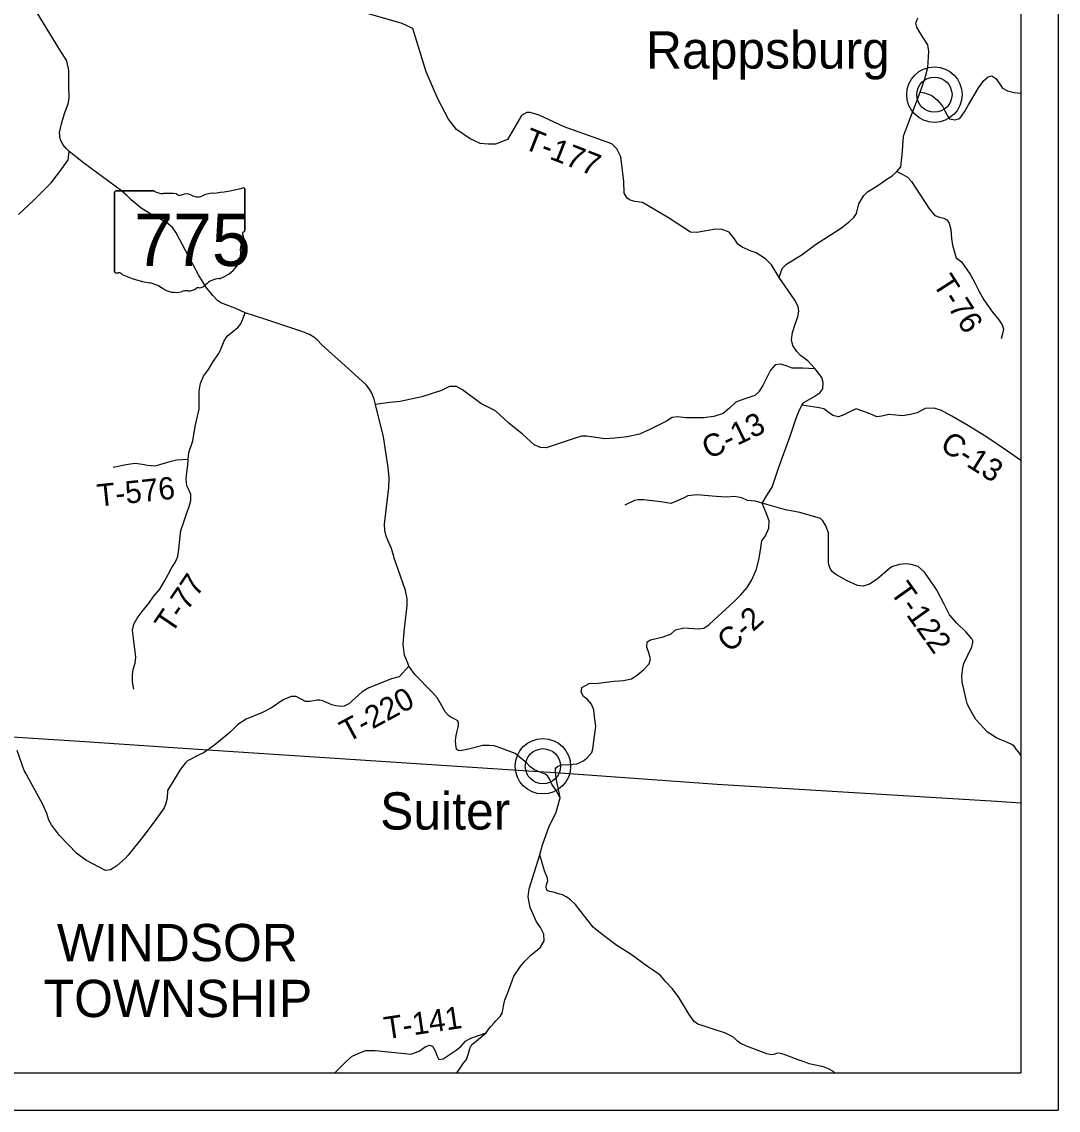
# Model space of a CAD drawing. Extents: x 0 to 34, y 0 to 22.
# Drawn here: x 6.219 to 9, y 14 to 16.922 of the extents above; entities that cross this region are included whole.
import ezdxf

# ---------------------------------------------------------------- set-up
doc = ezdxf.new("R2010")
doc.units = 0
for name, color, linetype in [('GM_X_County_Road', 7, 'Continuous'), ('GM_X_County_Road_Text', 7, 'Continuous'), ('GM_X_State_Route', 7, 'Continuous'), ('GM_X_State_Shield', 7, 'Continuous'), ('GM_X_Township', 7, 'Continuous'), ('GM_X_Township_Road', 7, 'Continuous'), ('GM_X_Township_Road_Text', 7, 'Continuous'), ('GM_X_Township_Text', 7, 'Continuous'), ('GM_X_Unincorporated', 7, 'Continuous'), ('SH_Data', 7, 'Continuous'), ('SH_Masking', 7, 'Continuous')]:
    doc.layers.add(name, color=color, linetype=linetype)

msp = doc.modelspace()

# ---------------------------------------------------------------- linework, layer by layer
at = {"layer": 'GM_X_County_Road'}
for points in [[(7.6514, 14.9162), (7.6514, 14.9181), (7.6562, 14.9229), (7.6669, 14.9268), (7.6883, 14.928), (7.7082, 14.9299), (7.7248, 14.9367), (7.7347, 14.9448), (7.7484, 14.96), (7.751, 14.9704), (7.7543, 14.9907), (7.7591, 15.0309), (7.7554, 15.0556), (7.754, 15.0746), (7.7476, 15.0902), (7.7356, 15.1032), (7.7258, 15.1109), (7.7201, 15.1223), (7.7214, 15.1316), (7.7217, 15.1344), (7.7411, 15.145), (7.7654, 15.1464), (7.8083, 15.1518), (7.8337, 15.1536), (7.8553, 15.1581), (7.8709, 15.1682), (7.8881, 15.1833), (7.9022, 15.1977), (7.9061, 15.2114), (7.9012, 15.2277), (7.8964, 15.2426), (7.8972, 15.257), (7.9063, 15.2626), (7.9398, 15.2708), (7.961, 15.2787), (7.9732, 15.2893), (7.9956, 15.2945), (8.0354, 15.292), (8.0495, 15.2938), (8.0624, 15.3032), (8.0769, 15.3165), (8.1078, 15.3448), (8.1306, 15.3652), (8.1482, 15.3837), (8.165, 15.4026), (8.1776, 15.4234), (8.1903, 15.4519), (8.1976, 15.4822), (8.2016, 15.5095), (8.2047, 15.5281), (8.2143, 15.5417), (8.2231, 15.5626), (8.224, 15.582), (8.2143, 15.6078), (8.2057, 15.6291), (8.2229, 15.6575), (8.2325, 15.6723), (8.2491, 15.7235), (8.281, 15.8091), (8.2972, 15.8573), (8.3041, 15.8755), (8.3123, 15.8927), (8.3172, 15.8993), (8.3465, 15.917), (8.3602, 15.9257), (8.3682, 15.9363), (8.369, 15.9534), (8.3661, 15.9663), (8.3477, 15.9897), (8.3277, 16.0117), (8.3084, 16.0258), (8.2982, 16.0369), (8.2881, 16.0522), (8.2847, 16.0674), (8.2871, 16.0875), (8.2929, 16.1068), (8.3014, 16.1292), (8.3041, 16.1451), (8.3019, 16.1573), (8.2937, 16.1744), (8.2512, 16.235), (8.2593, 16.2589), (8.2707, 16.2706), (8.313, 16.297), (8.3491, 16.3234), (8.391, 16.3501), (8.4184, 16.3686), (8.4409, 16.3859), (8.4519, 16.3958), (8.4588, 16.4071), (8.465, 16.4325), (8.4784, 16.4552), (8.4883, 16.4654), (8.5157, 16.482), (8.5378, 16.4971), (8.5545, 16.508), (8.5656, 16.5175), (8.5671, 16.5193), (8.5774, 16.5322), (8.5822, 16.574), (8.5835, 16.6039), (8.5859, 16.6172), (8.5963, 16.646), (8.6298, 16.7328), (8.6421, 16.7688), (8.6502, 16.7984), (8.6531, 16.8421), (8.6502, 16.8599), (8.637, 16.8805), (8.6265, 16.8961), (8.6209, 16.9068), (8.6179, 16.9174), (8.6233, 16.9322)], [(8.6298, 16.7328), (8.6411, 16.7305), (8.6612, 16.7236), (8.6763, 16.7113), (8.6891, 16.6946), (8.6954, 16.6824), (8.703, 16.6694), (8.7086, 16.6614), (8.7222, 16.6583), (8.7363, 16.6616), (8.7481, 16.6802), (8.7589, 16.6987), (8.7738, 16.7226), (8.7864, 16.7442), (8.8002, 16.7642), (8.8116, 16.7737), (8.8219, 16.7767), (8.8328, 16.7694), (8.8411, 16.7564), (8.8505, 16.7431), (8.8641, 16.7358), (8.8819, 16.7315), (8.9, 16.7302)], [(6.2103, 16.4042), (6.2518, 16.4439), (6.2979, 16.4889), (6.3266, 16.5267), (6.343, 16.5513), (6.3462, 16.5736)], [(8.3477, 15.9897), (8.3135, 15.992), (8.2862, 15.9918), (8.2726, 15.9968), (8.2559, 16.0026), (8.2404, 16.0007), (8.2278, 15.986), (8.2071, 15.9455), (8.1971, 15.9284), (8.1857, 15.9186), (8.1561, 15.9089), (8.1352, 15.9003), (8.118, 15.884), (8.1009, 15.8704), (8.0762, 15.8618), (8.0485, 15.8582), (8.0181, 15.8583), (8.0007, 15.858), (7.9791, 15.8612), (7.9639, 15.8594), (7.9491, 15.8496), (7.9046, 15.827), (7.8765, 15.815), (7.8431, 15.8076), (7.8104, 15.8035), (7.7835, 15.8022), (7.7528, 15.8069), (7.7342, 15.8092), (7.7206, 15.8093), (7.7035, 15.8041), (7.6264, 15.7779), (7.6108, 15.7791), (7.5934, 15.786), (7.5629, 15.815), (7.5255, 15.8445), (7.4897, 15.8769), (7.4503, 15.8965), (7.4013, 15.9332), (7.3858, 15.9427), (7.3664, 15.9428), (7.3451, 15.9319), (7.292, 15.9151), (7.2346, 15.9025), (7.2066, 15.8996), (7.1682, 15.8942)], [(8.9, 15.7435), (8.864, 15.7686), (8.8054, 15.8084), (8.7551, 15.8398), (8.7143, 15.8628), (8.6871, 15.8781), (8.6674, 15.8843), (8.6432, 15.8836), (8.6219, 15.8716), (8.604, 15.8671), (8.582, 15.8642), (8.5642, 15.8658), (8.5456, 15.8674), (8.527, 15.8626), (8.5137, 15.8615), (8.4956, 15.8692), (8.4577, 15.8823), (8.441, 15.8748), (8.425, 15.8661), (8.4102, 15.8613), (8.3955, 15.8648), (8.3819, 15.8743), (8.3713, 15.8827), (8.3584, 15.8855), (8.3123, 15.8927)], [(7.6635, 14.8385), (7.6593, 14.861), (7.6534, 14.8861), (7.6512, 14.9069), (7.6514, 14.9162)], [(7.3864, 14.1), (7.3864, 14.1006), (7.3949, 14.1131), (7.4029, 14.1252), (7.412, 14.1358), (7.4178, 14.1521), (7.4209, 14.1654), (7.4267, 14.1764), (7.4335, 14.1817), (7.4646, 14.2081), (7.4705, 14.2157), (7.4778, 14.2247), (7.4862, 14.2349), (7.4909, 14.2398), (7.497, 14.2463), (7.503, 14.2516), (7.5077, 14.2602), (7.5093, 14.2682), (7.5111, 14.2796), (7.5152, 14.296), (7.5226, 14.3137), (7.5396, 14.3597), (7.556, 14.3851), (7.5694, 14.4013), (7.5854, 14.4168), (7.5983, 14.4266), (7.6038, 14.4314), (7.6109, 14.4376), (7.6208, 14.4543), (7.6194, 14.4729), (7.6112, 14.49), (7.6003, 14.5056), (7.5831, 14.5441), (7.5779, 14.5726), (7.5803, 14.5942), (7.6086, 14.6853)]]:
    msp.add_lwpolyline(points, dxfattribs=at)
at = {"layer": 'GM_X_State_Route'}
msp.add_lwpolyline([(8.4009, 14.1), (8.3976, 14.1026), (8.3838, 14.1109), (8.3699, 14.1162), (8.3488, 14.1206), (8.3314, 14.1241), (8.3183, 14.1298), (8.3022, 14.1351), (8.265, 14.1498), (8.2545, 14.1523), (8.2458, 14.1529), (8.237, 14.1494), (8.2297, 14.1488), (8.2181, 14.1514), (8.1633, 14.1722), (8.1468, 14.1798), (8.1394, 14.1857), (8.1294, 14.1951), (8.1197, 14.2003), (8.1055, 14.2079), (8.0826, 14.2149), (8.0634, 14.2212), (8.0442, 14.2274), (8.0334, 14.2314), (8.0233, 14.2378), (8.0098, 14.2567), (7.9815, 14.3046), (7.9639, 14.3271), (7.9466, 14.3453), (7.9315, 14.3628), (7.917, 14.3731), (7.898, 14.3857), (7.8538, 14.4177), (7.8154, 14.4422), (7.7835, 14.4666), (7.7586, 14.4858), (7.7519, 14.4917), (7.7292, 14.5212), (7.7043, 14.5518), (7.6914, 14.5651), (7.6817, 14.5722), (7.6701, 14.5778), (7.6592, 14.5807), (7.6453, 14.5849), (7.6347, 14.5867), (7.6291, 14.5899), (7.6266, 14.5945), (7.6256, 14.5987), (7.6269, 14.6059), (7.6302, 14.6157), (7.63, 14.6229), (7.6214, 14.6421), (7.6086, 14.6853), (7.6165, 14.7124), (7.6334, 14.7598), (7.6525, 14.8003), (7.6635, 14.8385), (7.6525, 14.8585), (7.6413, 14.8754), (7.6351, 14.8892), (7.6295, 14.8976), (7.623, 14.9024), (7.6051, 14.9095), (7.5949, 14.9136), (7.5825, 14.9226), (7.5738, 14.9311), (7.5426, 14.9578), (7.5, 14.9733), (7.4861, 14.9778), (7.4732, 14.9793), (7.4558, 14.9786), (7.4173, 14.9694), (7.3997, 14.9653), (7.3936, 14.9643), (7.3895, 14.9652), (7.3858, 14.9695), (7.3838, 14.9805), (7.383, 14.9923), (7.3845, 15.0059), (7.3909, 15.0327), (7.3907, 15.0392), (7.3886, 15.0449), (7.3811, 15.0497), (7.3688, 15.0561), (7.3636, 15.0596), (7.3551, 15.0697), (7.3418, 15.0936), (7.3341, 15.106), (7.3191, 15.1234), (7.2748, 15.169), (7.2576, 15.1922), (7.2544, 15.1999), (7.2463, 15.221), (7.2421, 15.25), (7.2446, 15.2837), (7.2526, 15.3548), (7.253, 15.373), (7.2483, 15.3948), (7.2283, 15.4542), (7.2188, 15.4791), (7.216, 15.4887), (7.2112, 15.5078), (7.2065, 15.5178), (7.2008, 15.5301), (7.1966, 15.5408), (7.1932, 15.5561), (7.1921, 15.5728), (7.2035, 15.6712), (7.2046, 15.6974), (7.2023, 15.7255), (7.1894, 15.8075), (7.1682, 15.8942), (7.1644, 15.9087), (7.158, 15.9244), (7.1523, 15.9356), (7.1427, 15.9472), (7.1128, 15.9746), (7.0243, 16.0547), (7.0114, 16.068), (7.0029, 16.0746), (6.9906, 16.0818), (6.973, 16.0895), (6.8742, 16.1228), (6.8186, 16.1402), (6.7931, 16.1515), (6.7605, 16.1641), (6.7533, 16.1673), (6.7444, 16.1733), (6.7319, 16.1869), (6.7132, 16.2105), (6.6932, 16.2422), (6.6431, 16.3361), (6.6329, 16.3546), (6.6235, 16.3689), (6.6064, 16.3834), (6.572, 16.4006), (6.5396, 16.4212), (6.5129, 16.4439), (6.5007, 16.4552), (6.4867, 16.4678), (6.3844, 16.543), (6.3462, 16.5736), (6.3388, 16.5806), (6.3293, 16.5922), (6.3217, 16.6072), (6.3199, 16.6247), (6.3255, 16.6474), (6.3338, 16.6749), (6.3436, 16.7015), (6.3459, 16.7167), (6.345, 16.7535), (6.345, 16.7904), (6.3402, 16.8165), (6.3215, 16.8466), (6.2435, 16.9728)], dxfattribs=at)
at = {"layer": 'GM_X_State_Shield'}
for p, q in [((6.4677, 16.4637), (6.4677, 16.2511)), ((6.5736, 16.4673), (6.4711, 16.4673)), ((6.8177, 16.3614), (6.8177, 16.4726)), ((6.8177, 16.3614), (6.8177, 16.3614))]:
    msp.add_line(p, q, dxfattribs=at)
for centre, major_axis, start_param, end_param in [((6.4717, 16.4641), (0.00406, 0), 1.712693, 3.28349), ((6.598, 16.492), (0.0393, 0), 4.042523, 4.731795), ((6.6111, 16.348), (0.1412, 0), 1.404758, 1.657858), ((6.6431, 16.4652), (0.0113, 0), 3.836095, 5.185415), ((6.6598, 16.4407), (0.0236, 0), 0.950623, 2.079405), ((6.6903, 16.4744), (0.0284, 0), 4.081561, 5.145723), ((6.7404, 16.4024), (0.0747, 0), 1.699011, 2.107814), ((6.693, 16.7571), (0.3713, 0), 4.814394, 5.042369), ((6.8139, 16.4731), (0.0039, 0), 6.141152, 7.989035), ((6.8136, 16.361), (0.00417, 0), 5.05454, 6.418171), ((6.8168, 16.3532), (0.00603, 0), 1.883978, 3.671073), ((6.7785, 16.3392), (0.0362, 0), 5.934695, 6.695948), ((6.7138, 16.3007), (0.0929, 0), 5.101752, 6.440018), ((6.8317, 16.3149), (0.0263, 0), 2.387724, 3.262537), ((6.4717, 16.2506), (0.00409, 0), 3.00124, 4.508301), ((6.4723, 16.2724), (0.0312, 0), 4.665946, 4.897461), ((6.4787, 16.2388), (0.0113, 0), 0.519207, 1.627899), ((6.6209, 16.4298), (0.2681, 0), 4.195997, 4.488961), ((6.5409, 16.1556), (0.0839, 0), 0.823519, 1.323587), ((6.6886, 16.2305), (0.03, 0), 4.937069, 5.64225), ((6.753, 16.1914), (0.0509, 0), 1.647645, 2.488434), ((6.6317, 16.2378), (0.0532, 0), 4.026481, 4.996735), ((6.6624, 16.1643), (0.0437, 0), 1.495662, 1.94098), ((6.6663, 16.2219), (0.0284, 0), 4.691044, 5.507374), ((6.692, 16.2013), (0.00798, 0), 1.147584, 2.315152)]:
    msp.add_ellipse(centre, major_axis=major_axis, ratio=0.8, start_param=start_param, end_param=end_param, dxfattribs=at)
at = {"layer": 'GM_X_Township'}
msp.add_lwpolyline([(4.5386, 14.1), (4.5516, 14.3018), (4.5837, 14.7973), (4.6039, 15.1106), (4.7025, 15.1042), (4.9433, 15.0884), (5.1541, 15.0746), (5.2376, 15.0692), (5.6728, 15.0407), (6.0364, 15.013), (6.1929, 15.0025), (6.375, 14.9903), (6.7178, 14.9672), (7.6051, 14.9095), (7.6512, 14.9069), (8.0847, 14.8753), (8.8343, 14.8293), (8.9, 14.8252)], dxfattribs=at)
at = {"layer": 'GM_X_Township_Road'}
for points in [[(8.2512, 16.235), (8.2308, 16.2687), (8.2148, 16.2852), (8.1898, 16.3013), (8.1763, 16.3061), (8.1522, 16.3163), (8.1407, 16.3247), (8.1315, 16.3389), (8.1167, 16.3569), (8.098, 16.3642), (8.0811, 16.3646), (8.0303, 16.3555), (8.0129, 16.3568), (7.9542, 16.3957), (7.8844, 16.4364), (7.864, 16.4393), (7.8512, 16.4427), (7.8433, 16.4478), (7.8355, 16.4615), (7.834, 16.4926), (7.8266, 16.5591), (7.8159, 16.5808), (7.8022, 16.5939), (7.6744, 16.6396), (7.607, 16.6712), (7.5835, 16.6779), (7.5737, 16.6777), (7.56, 16.6703), (7.5226, 16.6059), (7.4902, 16.5934), (7.4716, 16.5929), (7.4492, 16.5951), (7.4217, 16.607), (7.3858, 16.6326), (7.3642, 16.6601), (7.3352, 16.7144), (7.3038, 16.7871), (7.2682, 16.9031), (7.24, 16.917), (7.1241, 16.9504)], [(8.5671, 16.5193), (8.5834, 16.512), (8.5955, 16.5048), (8.6064, 16.4929), (8.6549, 16.4186), (8.6692, 16.4019), (8.6813, 16.3969), (8.6931, 16.3945), (8.701, 16.3895), (8.7078, 16.3812), (8.7122, 16.3637), (8.714, 16.3401), (8.7165, 16.3222), (8.7217, 16.3032), (8.7266, 16.2876), (8.7402, 16.2769), (8.7545, 16.2564), (8.7642, 16.2419), (8.7766, 16.2205), (8.7871, 16.1992), (8.8003, 16.1756), (8.8108, 16.1604), (8.8232, 16.1425), (8.8402, 16.1215), (8.8492, 16.1081), (8.8529, 16.0967), (8.8498, 16.0804), (8.8472, 16.0706)], [(6.5195, 15.1301), (6.516, 15.1495), (6.5158, 15.1689), (6.5181, 15.1833), (6.5231, 15.2003), (6.5251, 15.2163), (6.519, 15.2668), (6.516, 15.2885), (6.5192, 15.3048), (6.5287, 15.3203), (6.5448, 15.3419), (6.5589, 15.3593), (6.5727, 15.3786), (6.5895, 15.399), (6.6021, 15.4202), (6.6128, 15.4399), (6.622, 15.4566), (6.6304, 15.4698), (6.6374, 15.4861), (6.6401, 15.5051), (6.6433, 15.5324), (6.6461, 15.5556), (6.653, 15.5764), (6.6615, 15.6037), (6.6681, 15.6204), (6.6723, 15.6363), (6.6724, 15.6527), (6.6683, 15.6637), (6.6616, 15.6763), (6.6598, 15.6934), (6.6618, 15.712), (6.6645, 15.7313), (6.6658, 15.7464), (6.6674, 15.7651), (6.6778, 15.7966), (6.6844, 15.8353), (6.6903, 15.8626), (6.6949, 15.8819), (6.6947, 15.9055), (6.6948, 15.9309), (6.6987, 15.9503), (6.7068, 15.97), (6.7198, 15.9882), (6.7321, 16.0094), (6.7473, 16.0309), (6.7535, 16.0427), (6.7623, 16.0647), (6.7704, 16.0775), (6.7856, 16.0904), (6.7989, 16.1006), (6.8066, 16.1108), (6.8186, 16.1402)], [(6.6658, 15.7464), (6.6339, 15.7451), (6.616, 15.7407), (6.6039, 15.7369), (6.5883, 15.7325), (6.5758, 15.7287), (6.5565, 15.7303), (6.5432, 15.7334), (6.522, 15.7362), (6.4988, 15.7321), (6.4643, 15.7255)], [(8.2057, 15.6291), (8.1875, 15.6345), (8.1659, 15.6369), (8.1508, 15.6438), (8.1311, 15.6477), (8.1087, 15.6456), (8.0825, 15.6476), (8.0302, 15.652), (8.0063, 15.6487), (7.9942, 15.6427), (7.9759, 15.6352), (7.9607, 15.6285), (7.9334, 15.6332), (7.8872, 15.6383), (7.8732, 15.6384), (7.8629, 15.6369), (7.8375, 15.6242)], [(8.6931, 15.3598), (8.6747, 15.396), (8.67, 15.4028), (8.6413, 15.4444), (8.6241, 15.459), (8.6055, 15.4646), (8.591, 15.4665), (8.5728, 15.4647), (8.5536, 15.4587), (8.5471, 15.4543), (8.5143, 15.4251), (8.4934, 15.4119), (8.477, 15.4063), (8.4678, 15.4073), (8.4611, 15.4083), (8.4336, 15.4206), (8.403, 15.4376), (8.3934, 15.4461), (8.3889, 15.4522), (8.3854, 15.4614), (8.3838, 15.4699), (8.3835, 15.5497), (8.3764, 15.5689), (8.3681, 15.5823), (8.3618, 15.5884), (8.3065, 15.6039), (8.268, 15.6113), (8.2057, 15.6291)], [(8.9, 14.9533), (8.8982, 14.9554), (8.8936, 14.9616), (8.8875, 14.9692), (8.8825, 14.9761), (8.8756, 14.9815), (8.8661, 14.9864), (8.8577, 14.9899), (8.8439, 14.9948), (8.8339, 14.9994), (8.8217, 15.0075), (8.8106, 15.0151), (8.7786, 15.0487), (8.7613, 15.0796), (8.7557, 15.092), (8.7531, 15.1021), (8.7426, 15.1499), (8.7418, 15.1655), (8.7444, 15.1875), (8.7463, 15.1989), (8.7684, 15.2438), (8.7709, 15.2561), (8.7706, 15.2601), (8.7681, 15.2652), (8.765, 15.2701), (8.7534, 15.2834), (8.7281, 15.3077), (8.7083, 15.3299), (8.6931, 15.3598)], [(7.2576, 15.1922), (7.2316, 15.1636), (7.2114, 15.1576), (7.1505, 15.1334), (7.1325, 15.1229), (7.0966, 15.0905), (7.0839, 15.0843), (7.0769, 15.0839), (7.0613, 15.0857), (7.0506, 15.0883), (7.0265, 15.0987), (7.0189, 15.1008), (7.0127, 15.1002), (6.992, 15.0966), (6.9798, 15.0967), (6.9549, 15.1101), (6.9416, 15.1102), (6.9204, 15.1011), (6.8894, 15.0804), (6.8646, 15.0675), (6.8212, 15.0494), (6.7988, 15.0354), (6.7771, 15.0139), (6.7374, 14.981), (6.7178, 14.9672), (6.7169, 14.9666)], [(6.7169, 14.9666), (6.7066, 14.9593), (6.6986, 14.9553), (6.6639, 14.9382), (6.6579, 14.9325), (6.645, 14.9154), (6.61, 14.8585), (6.6088, 14.8379), (6.6042, 14.8206), (6.6006, 14.8116), (6.5817, 14.784), (6.5449, 14.7349), (6.5044, 14.6842), (6.4969, 14.6768), (6.4889, 14.669), (6.4744, 14.6558), (6.4573, 14.6456), (6.4435, 14.6436), (6.3912, 14.6714), (6.3663, 14.6888), (6.32, 14.7378), (6.2989, 14.7663), (6.2911, 14.7786), (6.2858, 14.7963), (6.2757, 14.8202), (6.2323, 14.8996), (6.2305, 14.9025), (6.2253, 14.9114), (6.207, 14.9657)], [(7.0591, 14.1), (7.0726, 14.1139), (7.0901, 14.1317), (7.1057, 14.1449), (7.1232, 14.1532), (7.1418, 14.1603), (7.1676, 14.1606), (7.2461, 14.1522), (7.2631, 14.1506), (7.2851, 14.1585), (7.3015, 14.1705), (7.3129, 14.1747), (7.3212, 14.1716), (7.3284, 14.159), (7.3332, 14.1453), (7.3377, 14.1365), (7.3495, 14.1376), (7.3685, 14.1504), (7.3849, 14.161), (7.3971, 14.1708), (7.4097, 14.1852), (7.4237, 14.1931), (7.4646, 14.2081)]]:
    msp.add_lwpolyline(points, dxfattribs=at)
at = {"layer": 'GM_X_Unincorporated'}
for centre, radius in [((8.6678, 16.7259), 0.0744), ((8.6678, 16.7259), 0.0472), ((7.6173, 14.9233), 0.0744), ((7.6173, 14.9233), 0.0472)]:
    msp.add_circle(centre, radius, dxfattribs=at)
at = {"layer": 'SH_Data'}
for p, q in [((9, 21), (9, 14)), ((8.9, 20.9), (8.9, 14.1)), ((2.1, 14.1), (8.9, 14.1)), ((2, 14), (9, 14))]:
    msp.add_line(p, q, dxfattribs=at)
at = {"layer": 'SH_Masking'}
for p, q in [((6.4677, 16.2511), (6.4677, 16.4637)), ((6.4711, 16.4673), (6.5736, 16.4673)), ((6.8177, 16.4726), (6.8177, 16.3614)), ((6.815, 16.3578), (6.815, 16.3578))]:
    msp.add_line(p, q, dxfattribs=at)
for centre, major_axis, start_param, end_param in [((6.4717, 16.4641), (0.00406, 0), 1.712693, 3.28349), ((6.598, 16.492), (0.0393, 0), 4.042523, 4.731795), ((6.6111, 16.348), (0.1412, 0), 1.404758, 1.657858), ((6.6431, 16.4652), (0.0113, 0), 3.836095, 5.185415), ((6.6598, 16.4407), (0.0236, 0), 0.950623, 2.079405), ((6.6903, 16.4744), (0.0284, 0), 4.081561, 5.145723), ((6.7404, 16.4024), (0.0747, 0), 1.699011, 2.107814), ((6.693, 16.7571), (0.3713, 0), 4.814394, 5.042369), ((6.8139, 16.4731), (0.0039, 0), 6.141152, 7.989035), ((6.8136, 16.361), (0.00417, 0), 5.05454, 6.418171), ((6.8168, 16.3532), (0.00603, 0), 1.883978, 3.671073), ((6.7785, 16.3392), (0.0362, 0), 5.934695, 6.695948), ((6.7138, 16.3007), (0.0929, 0), 5.101752, 6.440018), ((6.8317, 16.3149), (0.0263, 0), 2.387724, 3.262537), ((6.4717, 16.2506), (0.00409, 0), 3.00124, 4.508301), ((6.4723, 16.2724), (0.0312, 0), 4.665946, 4.897461), ((6.4787, 16.2388), (0.0113, 0), 0.519207, 1.627899), ((6.6209, 16.4298), (0.2681, 0), 4.195997, 4.488961), ((6.5409, 16.1556), (0.0839, 0), 0.823519, 1.323587), ((6.6886, 16.2305), (0.03, 0), 4.937069, 5.64225), ((6.753, 16.1914), (0.0509, 0), 1.647645, 2.488434), ((6.6317, 16.2378), (0.0532, 0), 4.026481, 4.996735), ((6.6624, 16.1643), (0.0437, 0), 1.495662, 1.94098), ((6.6663, 16.2219), (0.0284, 0), 4.691044, 5.507374), ((6.692, 16.2013), (0.00798, 0), 1.147584, 2.315152)]:
    msp.add_ellipse(centre, major_axis=major_axis, ratio=0.8, start_param=start_param, end_param=end_param, dxfattribs=at)

# ---------------------------------------------------------------- texts
at = {"layer": 'GM_X_County_Road_Text'}
for s, rotation, p in [('C-13', 25.8992, (8.0624, 15.7461)), ('C-13', 327.8091, (8.6795, 15.7753)), ('C-2', 42.2396, (8.1183, 15.2258))]:
    msp.add_text(s, height=0.06, rotation=rotation, dxfattribs=at).set_placement(p)
at = {"layer": 'GM_X_State_Shield'}
msp.add_text('775', height=0.14004, dxfattribs=at).set_placement((6.5207, 16.2661))
at = {"layer": 'GM_X_Township_Road_Text'}
for s, rotation, p in [('T-177', 338.4048, (7.5618, 16.5825)), ('T-76', 302.7482, (8.6617, 16.2187)), ('T-576', 5.9274, (6.4239, 15.62)), ('T-77', 55.7742, (6.6206, 15.2759)), ('T-122', 305.3744, (8.547, 15.3914)), ('T-220', 28.4319, (7.0932, 14.9858)), ('T-141', 8.4315, (7.1957, 14.1902))]:
    msp.add_text(s, height=0.06, rotation=rotation, dxfattribs=at).set_placement(p)
at = {"layer": 'GM_X_Township_Text'}
for s, p in [('WINDSOR', (6.3133, 14.4)), ('TOWNSHIP', (6.2778, 14.25))]:
    msp.add_text(s, height=0.1, dxfattribs=at).set_placement(p)
at = {"layer": 'GM_X_Unincorporated'}
for s, p in [('Rappsburg', (7.8938, 16.7959)), ('Suiter', (7.1805, 14.7533))]:
    msp.add_text(s, height=0.1, dxfattribs=at).set_placement(p)

doc.saveas('drawing.dxf')
